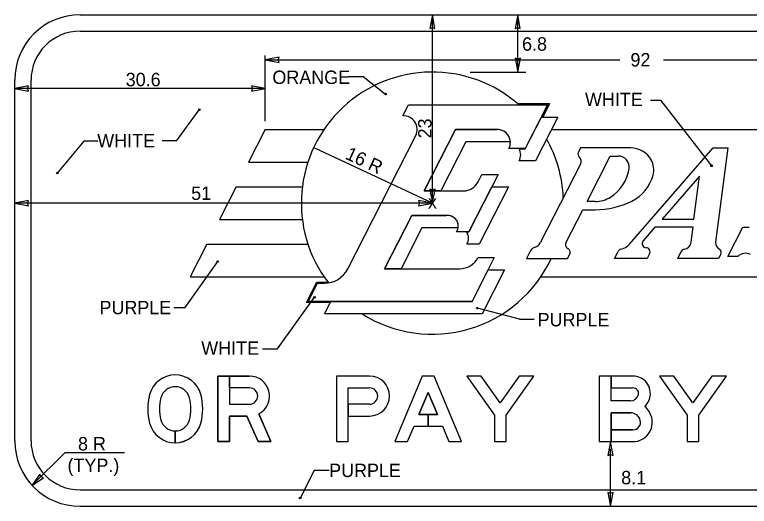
# Model space of a CAD drawing. Extents: x 319706 to 320346, y 1621790 to 1622121.
# Drawn here: x 319726.9 to 319803.6, y 1621939.2 to 1621990.5 of the extents above; entities that cross this region are included whole.
import ezdxf

# ---------------------------------------------------------------- set-up
doc = ezdxf.new("R2010")
doc.units = 0
for name, color, linetype in [('1', 7, 'Continuous'), ('52', 7, 'Continuous'), ('GSBWFill', 7, 'Continuous'), ('GSColorFill', 7, 'Continuous'), ('GSOutline', 7, 'Continuous'), ('SignPanel', 7, 'Continuous')]:
    doc.layers.add(name, color=color, linetype=linetype)

msp = doc.modelspace()

# ---------------------------------------------------------------- linework, layer by layer
at = {"layer": '1'}
for p, q in [((319770.499, 1621970.875), (319770.499, 1621990.54)), ((319779.405, 1621984.554), (319779.405, 1621990.539)), ((319753.057, 1621979.425), (319753.057, 1621986.265)), ((319753.057, 1621985.838), (319790.061, 1621985.838)), ((319794.612, 1621985.838), (319831.717, 1621985.838)), ((319761.71, 1621984.076), (319763.257, 1621984.076)), ((319763.257, 1621984.076), (319765.616, 1621982.255)), ((319774.432, 1621984.554), (319780.26, 1621984.554)), ((319753.057, 1621982.845), (319726.894, 1621982.845)), ((319793.284, 1621981.616), (319794.302, 1621981.616)), ((319794.302, 1621981.616), (319799.636, 1621974.776)), ((319743.826, 1621977.424), (319746.164, 1621980.623)), ((319734.126, 1621977.354), (319731.341, 1621974.017)), ((319735.572, 1621977.354), (319734.126, 1621977.354)), ((319742.279, 1621977.424), (319743.826, 1621977.424)), ((319770.499, 1621970.874), (319758.222, 1621976.599)), ((319755.462, 1621970.875), (319726.894, 1621970.875)), ((319770.499, 1621970.875), (319755.462, 1621970.875)), ((319744.686, 1621959.996), (319748.083, 1621964.786)), ((319754.313, 1621955.659), (319758.192, 1621961.049)), ((319743.5, 1621959.996), (319744.686, 1621959.996)), ((319779.586, 1621958.768), (319775.195, 1621959.917)), ((319779.586, 1621958.768), (319781.134, 1621958.768)), ((319752.765, 1621955.659), (319754.313, 1621955.659)), ((319789.098, 1621939.239), (319789.098, 1621945.224)), ((319728.692, 1621941.392), (319732.154, 1621944.855)), ((319732.154, 1621944.855), (319738.346, 1621944.855)), ((319758.163, 1621942.957), (319756.692, 1621940.103)), ((319759.725, 1621942.957), (319758.163, 1621942.957))]:
    msp.add_line(p, q, dxfattribs=at)
for centre in [(319765.616, 1621982.254), (319746.164, 1621980.621), (319799.635, 1621974.775), (319731.34, 1621974.016), (319748.083, 1621964.784), (319758.192, 1621961.048), (319775.195, 1621959.915), (319775.195, 1621959.915), (319756.692, 1621940.103)]:
    msp.add_circle(centre, 0.0855, dxfattribs=at)
at = {"layer": '52'}
for p, q in [((319770.499, 1621990.54), (319770.219, 1621989.09)), ((319770.769, 1621989.09), (319770.499, 1621990.54)), ((319779.405, 1621990.539), (319779.125, 1621989.089)), ((319779.675, 1621989.089), (319779.405, 1621990.539)), ((319770.219, 1621989.09), (319770.499, 1621989.2)), ((319770.499, 1621989.2), (319770.769, 1621989.09)), ((319779.125, 1621989.089), (319779.405, 1621989.199)), ((319779.405, 1621989.199), (319779.675, 1621989.089)), ((319754.507, 1621986.108), (319753.057, 1621985.838)), ((319753.057, 1621985.838), (319754.507, 1621985.558)), ((319754.397, 1621985.838), (319754.507, 1621986.108)), ((319754.507, 1621985.558), (319754.397, 1621985.838)), ((319779.405, 1621985.894), (319779.135, 1621986.004)), ((319779.135, 1621986.004), (319779.405, 1621984.554)), ((319779.405, 1621984.554), (319779.685, 1621986.004)), ((319779.685, 1621986.004), (319779.405, 1621985.894)), ((319728.344, 1621983.115), (319726.894, 1621982.845)), ((319726.894, 1621982.845), (319728.344, 1621982.565)), ((319728.234, 1621982.845), (319728.344, 1621983.115)), ((319728.344, 1621982.565), (319728.234, 1621982.845)), ((319753.057, 1621982.845), (319751.607, 1621983.125)), ((319751.607, 1621983.125), (319751.717, 1621982.845)), ((319751.717, 1621982.845), (319751.607, 1621982.575)), ((319751.607, 1621982.575), (319753.057, 1621982.845)), ((319770.499, 1621972.215), (319770.229, 1621972.325)), ((319770.229, 1621972.325), (319770.499, 1621970.875)), ((319770.499, 1621970.875), (319770.779, 1621972.325)), ((319770.779, 1621972.325), (319770.499, 1621972.215)), ((319728.344, 1621971.145), (319726.894, 1621970.875)), ((319728.234, 1621970.875), (319728.344, 1621971.145)), ((319770.499, 1621970.875), (319769.049, 1621971.155)), ((319769.049, 1621971.155), (319769.159, 1621970.875)), ((319726.894, 1621970.875), (319728.344, 1621970.595)), ((319728.344, 1621970.595), (319728.234, 1621970.875)), ((319769.159, 1621970.875), (319769.049, 1621970.605)), ((319769.049, 1621970.605), (319770.499, 1621970.875)), ((319789.098, 1621945.988), (319788.818, 1621944.538)), ((319789.368, 1621944.538), (319789.098, 1621945.988)), ((319788.818, 1621944.538), (319789.098, 1621944.648)), ((319789.098, 1621944.648), (319789.368, 1621944.538)), ((319729.526, 1621942.608), (319728.692, 1621941.392)), ((319729.639, 1621942.34), (319729.526, 1621942.608)), ((319728.692, 1621941.392), (319729.915, 1621942.219)), ((319729.915, 1621942.219), (319729.639, 1621942.34)), ((319789.098, 1621940.579), (319788.828, 1621940.689)), ((319788.828, 1621940.689), (319789.098, 1621939.239)), ((319789.098, 1621939.239), (319789.378, 1621940.689)), ((319789.378, 1621940.689), (319789.098, 1621940.579))]:
    msp.add_line(p, q, dxfattribs=at)
at = {"layer": 'GSBWFill'}
for p, q in [((319761.713, 1621951.598), (319763.936, 1621951.598)), ((319743.651, 1621945.868), (319743.651, 1621947.099)), ((319743.651, 1621947.099), (319743.651, 1621945.868))]:
    msp.add_line(p, q, dxfattribs=at)
for points in [[(319752.38, 1621948.897), (319753.64, 1621945.988), (319752.298, 1621945.988), (319751.143, 1621948.656), (319749.33, 1621948.656), (319749.33, 1621945.988), (319748.098, 1621945.988), (319748.098, 1621952.829), (319749.329, 1621952.829), (319749.33, 1621949.887), (319751.406, 1621949.887)], [(319749.33, 1621951.598), (319749.33, 1621952.829), (319751.406, 1621952.829)], [(319763.936, 1621952.829), (319760.481, 1621952.829), (319760.481, 1621945.988), (319761.713, 1621945.988), (319761.713, 1621951.598)], [(319791.174, 1621950.229), (319789.148, 1621950.229), (319789.148, 1621952.829), (319787.916, 1621952.829), (319787.916, 1621945.988), (319789.148, 1621945.988)], [(319791.439, 1621952.829), (319789.148, 1621952.829), (319789.148, 1621951.598), (319791.439, 1621951.598)], [(319751.406, 1621951.598), (319749.33, 1621951.598)], [(319763.936, 1621949.887), (319761.713, 1621949.887), (319761.713, 1621948.656), (319763.936, 1621948.656)], [(319789.148, 1621945.988), (319789.148, 1621948.998), (319791.174, 1621948.998)], [(319791.439, 1621947.219), (319789.148, 1621947.219), (319789.148, 1621945.988), (319791.439, 1621945.988)]]:
    msp.add_lwpolyline(points, dxfattribs=at)
for points in [[(319771.021, 1621948.827), (319770.06, 1621948.827), (319770.06, 1621947.595), (319771.538, 1621947.595), (319772.213, 1621945.988), (319773.549, 1621945.988), (319770.675, 1621952.829), (319769.444, 1621952.829), (319766.57, 1621945.988), (319767.906, 1621945.988), (319768.581, 1621947.595), (319770.06, 1621947.595), (319770.06, 1621948.827), (319769.099, 1621948.827), (319770.06, 1621951.115)], [(319778.201, 1621948.758), (319781.074, 1621952.829), (319779.567, 1621952.829), (319777.585, 1621950.022), (319775.603, 1621952.829), (319774.096, 1621952.829), (319776.97, 1621948.758), (319776.97, 1621945.988), (319778.201, 1621945.988)], [(319798.315, 1621948.758), (319801.189, 1621952.829), (319799.681, 1621952.829), (319797.699, 1621950.022), (319795.718, 1621952.829), (319794.21, 1621952.829), (319797.084, 1621948.758), (319797.084, 1621945.988), (319798.315, 1621945.988)]]:
    msp.add_lwpolyline(points, close=True, dxfattribs=at)
for centre, radius, start, end in [((319743.651, 1621950.176), 2.773, 14.96177, 165.03823), ((319751.406, 1621950.742), 2.087, 297.837, 90), ((319791.439, 1621951.016), 1.813, 345.52249, 90), ((319743.651, 1621950.176), 1.541, 14.96177, 165.03823), ((319751.406, 1621950.742), 0.855, 270, 90), ((319791.439, 1621951.016), 0.582, 345.52249, 90), ((319746.525, 1621949.408), 5.747, 165.03823, 194.96177), ((319746.525, 1621949.408), 4.515, 165.03823, 194.96177), ((319740.778, 1621949.408), 4.515, 345.03823, 14.96177), ((319740.778, 1621949.408), 5.747, 345.03823, 14.96177), ((319791.174, 1621951.084), 0.855, 270, 345.52249), ((319791.174, 1621951.084), 2.087, 316.7114, 345.52249), ((319791.174, 1621947.937), 2.292, 14.47751, 48.4921), ((319791.174, 1621947.937), 1.06, 14.47751, 90), ((319743.651, 1621948.64), 1.541, 194.96177, 270), ((319743.651, 1621948.64), 1.541, 270.01272, 345.03823), ((319791.439, 1621948.006), 2.018, 270, 14.47751), ((319791.439, 1621948.006), 0.787, 270, 14.47751), ((319743.651, 1621948.64), 2.773, 194.96177, 270), ((319743.651, 1621948.64), 2.773, 270.00707, 345.03823)]:
    msp.add_arc(centre, radius, start, end, dxfattribs=at)
for major_axis in [(0, 2.087), (0, 0.855)]:
    msp.add_ellipse((319763.936, 1621950.742), major_axis=major_axis, ratio=0.999994, start_param=3.141593, end_param=6.283185, dxfattribs=at)
at = {"layer": 'GSColorFill'}
for p, q in [((319761.713, 1621951.598), (319763.936, 1621951.598)), ((319743.651, 1621945.868), (319743.651, 1621947.099)), ((319743.651, 1621947.099), (319743.651, 1621945.868))]:
    msp.add_line(p, q, dxfattribs=at)
for points in [[(319752.38, 1621948.897), (319753.64, 1621945.988), (319752.298, 1621945.988), (319751.143, 1621948.656), (319749.33, 1621948.656), (319749.33, 1621945.988), (319748.098, 1621945.988), (319748.098, 1621952.829), (319749.329, 1621952.829), (319749.33, 1621949.887), (319751.406, 1621949.887)], [(319749.33, 1621951.598), (319749.33, 1621952.829), (319751.406, 1621952.829)], [(319763.936, 1621952.829), (319760.481, 1621952.829), (319760.481, 1621945.988), (319761.713, 1621945.988), (319761.713, 1621951.598)], [(319791.174, 1621950.229), (319789.148, 1621950.229), (319789.148, 1621952.829), (319787.916, 1621952.829), (319787.916, 1621945.988), (319789.148, 1621945.988)], [(319791.439, 1621952.829), (319789.148, 1621952.829), (319789.148, 1621951.598), (319791.439, 1621951.598)], [(319751.406, 1621951.598), (319749.33, 1621951.598)], [(319763.936, 1621949.887), (319761.713, 1621949.887), (319761.713, 1621948.656), (319763.936, 1621948.656)], [(319789.148, 1621945.988), (319789.148, 1621948.998), (319791.174, 1621948.998)], [(319791.439, 1621947.219), (319789.148, 1621947.219), (319789.148, 1621945.988), (319791.439, 1621945.988)]]:
    msp.add_lwpolyline(points, dxfattribs=at)
for points in [[(319771.021, 1621948.827), (319770.06, 1621948.827), (319770.06, 1621947.595), (319771.538, 1621947.595), (319772.213, 1621945.988), (319773.549, 1621945.988), (319770.675, 1621952.829), (319769.444, 1621952.829), (319766.57, 1621945.988), (319767.906, 1621945.988), (319768.581, 1621947.595), (319770.06, 1621947.595), (319770.06, 1621948.827), (319769.099, 1621948.827), (319770.06, 1621951.115)], [(319778.201, 1621948.758), (319781.074, 1621952.829), (319779.567, 1621952.829), (319777.585, 1621950.022), (319775.603, 1621952.829), (319774.096, 1621952.829), (319776.97, 1621948.758), (319776.97, 1621945.988), (319778.201, 1621945.988)], [(319798.315, 1621948.758), (319801.189, 1621952.829), (319799.681, 1621952.829), (319797.699, 1621950.022), (319795.718, 1621952.829), (319794.21, 1621952.829), (319797.084, 1621948.758), (319797.084, 1621945.988), (319798.315, 1621945.988)]]:
    msp.add_lwpolyline(points, close=True, dxfattribs=at)
for centre, radius, start, end in [((319743.651, 1621950.176), 2.773, 14.96177, 165.03823), ((319751.406, 1621950.742), 2.087, 297.837, 90), ((319791.439, 1621951.016), 1.813, 345.52249, 90), ((319743.651, 1621950.176), 1.541, 14.96177, 165.03823), ((319751.406, 1621950.742), 0.855, 270, 90), ((319791.439, 1621951.016), 0.582, 345.52249, 90), ((319746.525, 1621949.408), 5.747, 165.03823, 194.96177), ((319746.525, 1621949.408), 4.515, 165.03823, 194.96177), ((319740.778, 1621949.408), 4.515, 345.03823, 14.96177), ((319740.778, 1621949.408), 5.747, 345.03823, 14.96177), ((319791.174, 1621951.084), 0.855, 270, 345.52249), ((319791.174, 1621951.084), 2.087, 316.7114, 345.52249), ((319791.174, 1621947.937), 2.292, 14.47751, 48.4921), ((319791.174, 1621947.937), 1.06, 14.47751, 90), ((319743.651, 1621948.64), 1.541, 194.96177, 270), ((319743.651, 1621948.64), 1.541, 270.01272, 345.03823), ((319791.439, 1621948.006), 2.018, 270, 14.47751), ((319791.439, 1621948.006), 0.787, 270, 14.47751), ((319743.651, 1621948.64), 2.773, 194.96177, 270), ((319743.651, 1621948.64), 2.773, 270.00707, 345.03823)]:
    msp.add_arc(centre, radius, start, end, dxfattribs=at)
for major_axis in [(0, 2.087), (0, 0.855)]:
    msp.add_ellipse((319763.936, 1621950.742), major_axis=major_axis, ratio=0.999994, start_param=3.141593, end_param=6.283185, dxfattribs=at)
at = {"layer": 'GSOutline'}
for p, q in [((319761.713, 1621951.598), (319763.936, 1621951.598)), ((319761.713, 1621948.656), (319763.936, 1621948.656)), ((319787.916, 1621945.988), (319791.439, 1621945.988))]:
    msp.add_line(p, q, dxfattribs=at)
for points in [[(319751.406, 1621952.829), (319748.098, 1621952.829), (319748.098, 1621945.988), (319749.33, 1621945.988), (319749.33, 1621948.656), (319751.143, 1621948.656), (319752.298, 1621945.988), (319753.64, 1621945.988), (319752.38, 1621948.897)], [(319763.936, 1621952.829), (319760.481, 1621952.829), (319760.481, 1621945.988), (319761.713, 1621945.988), (319761.713, 1621948.656)], [(319791.439, 1621952.829), (319787.916, 1621952.829), (319787.916, 1621945.988)], [(319751.406, 1621951.598), (319749.33, 1621951.598), (319749.33, 1621949.887), (319751.406, 1621949.887)], [(319763.936, 1621949.887), (319761.713, 1621949.887), (319761.713, 1621951.598)], [(319791.174, 1621950.229), (319789.148, 1621950.229), (319789.148, 1621951.598), (319791.439, 1621951.598)], [(319791.174, 1621948.998), (319789.148, 1621948.998), (319789.148, 1621947.219), (319791.439, 1621947.219)]]:
    msp.add_lwpolyline(points, dxfattribs=at)
for points in [[(319768.581, 1621947.595), (319771.538, 1621947.595), (319772.213, 1621945.988), (319773.549, 1621945.988), (319770.675, 1621952.829), (319769.444, 1621952.829), (319766.57, 1621945.988), (319767.906, 1621945.988)], [(319778.201, 1621948.758), (319781.074, 1621952.829), (319779.567, 1621952.829), (319777.585, 1621950.022), (319775.603, 1621952.829), (319774.096, 1621952.829), (319776.97, 1621948.758), (319776.97, 1621945.988), (319778.201, 1621945.988)], [(319798.315, 1621948.758), (319801.189, 1621952.829), (319799.681, 1621952.829), (319797.699, 1621950.022), (319795.718, 1621952.829), (319794.21, 1621952.829), (319797.084, 1621948.758), (319797.084, 1621945.988), (319798.315, 1621945.988)], [(319771.021, 1621948.827), (319770.06, 1621951.115), (319769.099, 1621948.827)]]:
    msp.add_lwpolyline(points, close=True, dxfattribs=at)
for centre, radius, start, end in [((319743.651, 1621950.176), 2.773, 14.96177, 165.03823), ((319751.406, 1621950.742), 2.087, 297.837, 90), ((319791.439, 1621951.016), 1.813, 345.52249, 90), ((319743.651, 1621950.176), 1.541, 14.96177, 165.03823), ((319751.406, 1621950.742), 0.855, 270, 90), ((319791.439, 1621951.016), 0.582, 345.52249, 90), ((319746.525, 1621949.408), 5.747, 165.03823, 194.96177), ((319746.525, 1621949.408), 4.515, 165.03823, 194.96177), ((319740.778, 1621949.408), 4.515, 345.03823, 14.96177), ((319740.778, 1621949.408), 5.747, 345.03823, 14.96177), ((319791.174, 1621951.084), 0.855, 270, 345.52249), ((319791.174, 1621951.084), 2.087, 316.7114, 345.52249), ((319791.174, 1621947.937), 2.292, 14.47751, 48.4921), ((319791.174, 1621947.937), 1.06, 14.47751, 90), ((319743.651, 1621948.64), 1.541, 194.96177, 345.03823), ((319791.439, 1621948.006), 2.018, 270, 14.47751), ((319791.439, 1621948.006), 0.787, 270, 14.47751), ((319743.651, 1621948.64), 2.773, 194.96177, 345.03823)]:
    msp.add_arc(centre, radius, start, end, dxfattribs=at)
for major_axis in [(0, 2.087), (0, 0.855)]:
    msp.add_ellipse((319763.936, 1621950.742), major_axis=major_axis, ratio=0.999994, start_param=3.141593, end_param=6.283185, dxfattribs=at)
at = {"layer": 'SignPanel'}
for p, q in [((319733.734, 1621990.539), (319843.174, 1621990.539)), ((319733.734, 1621988.829), (319843.174, 1621988.829)), ((319726.894, 1621946.079), (319726.894, 1621983.699)), ((319728.604, 1621946.079), (319728.604, 1621983.699)), ((319767.405, 1621979.987), (319767.988, 1621981.134)), ((319767.988, 1621981.134), (319782.523, 1621981.134)), ((319779.399, 1621981.262), (319782.732, 1621981.262)), ((319782.523, 1621981.134), (319780.195, 1621976.563)), ((319782.732, 1621981.262), (319782.013, 1621979.852)), ((319780.192, 1621976.558), (319781.871, 1621979.852)), ((319780.192, 1621976.558), (319781.871, 1621979.852)), ((319783.598, 1621979.852), (319781.268, 1621975.28)), ((319783.598, 1621979.852), (319781.268, 1621975.28)), ((319781.871, 1621979.852), (319783.598, 1621979.852)), ((319781.871, 1621979.852), (319783.598, 1621979.852)), ((319753.057, 1621978.569), (319751.316, 1621975.149)), ((319753.057, 1621978.569), (319759.188, 1621978.569)), ((319761.66, 1621964.012), (319768.756, 1621977.94)), ((319772.914, 1621978.569), (319769.647, 1621972.157)), ((319769.647, 1621972.157), (319772.914, 1621978.569)), ((319769.647, 1621972.157), (319772.914, 1621978.569)), ((319777.272, 1621978.569), (319772.914, 1621978.569)), ((319772.914, 1621978.569), (319777.272, 1621978.569)), ((319772.914, 1621978.569), (319777.272, 1621978.569)), ((319782.943, 1621978.569), (319831.717, 1621978.569)), ((319773.988, 1621977.287), (319771.374, 1621972.157)), ((319773.988, 1621977.287), (319771.374, 1621972.157)), ((319778.639, 1621977.287), (319773.988, 1621977.287)), ((319778.639, 1621977.287), (319773.988, 1621977.287)), ((319780.195, 1621976.563), (319778.484, 1621976.563)), ((319779.556, 1621976.558), (319780.192, 1621976.558)), ((319779.556, 1621976.558), (319780.192, 1621976.558)), ((319785.974, 1621976.645), (319785.741, 1621976.189)), ((319791.21, 1621976.645), (319785.974, 1621976.645)), ((319791.079, 1621966.604), (319799.81, 1621976.645)), ((319799.81, 1621976.645), (319801.349, 1621976.645)), ((319801.349, 1621976.645), (319800.069, 1621966.806)), ((319786.645, 1621971.045), (319789.064, 1621975.79)), ((319789.064, 1621975.79), (319789.888, 1621975.79)), ((319751.316, 1621975.149), (319757.504, 1621975.149)), ((319781.268, 1621975.28), (319779.558, 1621975.28)), ((319781.268, 1621975.28), (319779.558, 1621975.28)), ((319785.989, 1621975.029), (319781.755, 1621966.721)), ((319777.367, 1621973.867), (319774.318, 1621967.882)), ((319775.261, 1621973.09), (319775.657, 1621973.867)), ((319775.657, 1621973.867), (319777.367, 1621973.867)), ((319798.378, 1621973.696), (319794.475, 1621969.206)), ((319797.794, 1621969.206), (319798.378, 1621973.696)), ((319750.011, 1621972.584), (319748.27, 1621969.164)), ((319750.011, 1621972.584), (319756.925, 1621972.584)), ((319774.318, 1621967.882), (319776.714, 1621972.584)), ((319774.318, 1621967.882), (319776.714, 1621972.584)), ((319778.441, 1621972.584), (319775.391, 1621966.599)), ((319778.441, 1621972.584), (319775.391, 1621966.599)), ((319776.714, 1621972.584), (319778.441, 1621972.584)), ((319776.714, 1621972.584), (319778.441, 1621972.584)), ((319769.647, 1621972.157), (319773.738, 1621972.157)), ((319771.374, 1621972.157), (319769.647, 1621972.157)), ((319771.374, 1621972.157), (319769.647, 1621972.157)), ((319787.492, 1621971.045), (319786.645, 1621971.045)), ((319784.441, 1621966.721), (319786.209, 1621970.19)), ((319786.209, 1621970.19), (319787.492, 1621970.19)), ((319768.341, 1621969.592), (319765.509, 1621964.034)), ((319765.509, 1621964.034), (319768.341, 1621969.592)), ((319765.509, 1621964.034), (319768.341, 1621969.592)), ((319772.093, 1621969.592), (319768.341, 1621969.592)), ((319768.341, 1621969.592), (319771.932, 1621969.58)), ((319768.341, 1621969.592), (319771.932, 1621969.58)), ((319748.27, 1621969.164), (319756.925, 1621969.164)), ((319794.475, 1621969.206), (319797.794, 1621969.206)), ((319769.413, 1621968.306), (319767.236, 1621964.034)), ((319769.413, 1621968.306), (319767.236, 1621964.034)), ((319773.188, 1621968.294), (319769.413, 1621968.306)), ((319773.188, 1621968.294), (319769.413, 1621968.306)), ((319774.318, 1621967.882), (319773.03, 1621967.882)), ((319774.049, 1621967.882), (319774.318, 1621967.882)), ((319774.049, 1621967.882), (319774.318, 1621967.882)), ((319793.734, 1621968.351), (319792.494, 1621966.927)), ((319797.707, 1621968.351), (319793.734, 1621968.351)), ((319797.504, 1621966.806), (319797.707, 1621968.351)), ((319801.343, 1621965.317), (319802.895, 1621968.364)), ((319802.895, 1621968.364), (319803.582, 1621968.364)), ((319746.964, 1621966.599), (319745.223, 1621963.179)), ((319746.964, 1621966.599), (319757.504, 1621966.599)), ((319775.391, 1621966.599), (319774.109, 1621966.599)), ((319775.391, 1621966.599), (319774.109, 1621966.599)), ((319780.716, 1621965.857), (319780.332, 1621965.102)), ((319789.506, 1621965.102), (319789.878, 1621965.834)), ((319793.178, 1621965.596), (319792.926, 1621965.102)), ((319796.104, 1621965.102), (319796.482, 1621965.845)), ((319776.963, 1621965.185), (319774.634, 1621960.614)), ((319775.252, 1621965.185), (319776.963, 1621965.185)), ((319780.332, 1621965.102), (319784.607, 1621965.102)), ((319784.607, 1621965.102), (319784.839, 1621965.56)), ((319792.926, 1621965.102), (319789.506, 1621965.102)), ((319800.379, 1621965.102), (319796.104, 1621965.102)), ((319800.604, 1621965.543), (319800.379, 1621965.102)), ((319802.382, 1621965.317), (319801.343, 1621965.317)), ((319765.509, 1621964.034), (319773.356, 1621964.034)), ((319767.236, 1621964.034), (319765.509, 1621964.034)), ((319767.236, 1621964.034), (319765.509, 1621964.034)), ((319774.634, 1621960.614), (319776.309, 1621963.903)), ((319774.634, 1621960.614), (319776.309, 1621963.903)), ((319778.037, 1621963.903), (319775.707, 1621959.332)), ((319778.037, 1621963.903), (319775.707, 1621959.332)), ((319776.309, 1621963.903), (319778.037, 1621963.903)), ((319776.309, 1621963.903), (319778.037, 1621963.903)), ((319745.223, 1621963.179), (319759.188, 1621963.179)), ((319757.351, 1621960.502), (319758.435, 1621962.63)), ((319757.534, 1621960.614), (319758.504, 1621962.518)), ((319758.435, 1621962.63), (319759.222, 1621962.63)), ((319758.504, 1621962.518), (319759.222, 1621962.518)), ((319781.809, 1621963.179), (319823.875, 1621963.179)), ((319759.84, 1621960.502), (319757.351, 1621960.502)), ((319774.634, 1621960.614), (319757.534, 1621960.614)), ((319759.244, 1621959.332), (319759.897, 1621960.614)), ((319759.244, 1621959.332), (319759.897, 1621960.614)), ((319759.897, 1621960.614), (319774.634, 1621960.614)), ((319759.897, 1621960.614), (319774.634, 1621960.614)), ((319775.707, 1621959.332), (319759.244, 1621959.332)), ((319775.707, 1621959.332), (319759.244, 1621959.332)), ((319733.734, 1621940.949), (319843.174, 1621940.949)), ((319733.734, 1621939.239), (319843.174, 1621939.239))]:
    msp.add_line(p, q, dxfattribs=at)
for centre, radius, start, end in [((319733.733, 1621983.698), 6.84, 90, 180), ((319733.733, 1621983.698), 5.13, 90, 180), ((319770.498, 1621970.873), 13.68, 48.59038, 217.4727), ((319767.498, 1621978.579), 1.411, 332.99985, 93.80449), ((319777.273, 1621977.2), 1.368, 332.20885, 90), ((319777.273, 1621977.2), 1.368, 3.58332, 90), ((319777.273, 1621977.2), 1.368, 3.58332, 90), ((319770.498, 1621970.873), 13.68, 2.42356, 29.27706), ((319778.347, 1621975.917), 1.368, 332.20885, 27.91266), ((319778.347, 1621975.917), 1.368, 332.20885, 27.91266), ((319791.21, 1621974.207), 2.437, 29.43149, 90), ((319786.121, 1621975.994), 0.428, 152.97842, 231.16017), ((319785.531, 1621975.261), 0.513, 333.00266, 51.16017), ((319789.887, 1621974.635), 1.154, 351.07601, 90), ((319791.47, 1621974.354), 2.138, 344.70738, 29.43149), ((319786.804, 1621975.119), 4.275, 302.42062, 351.07601), ((319789.409, 1621974.918), 4.275, 296.64315, 344.70738), ((319773.738, 1621973.865), 1.71, 270, 332.98829), ((319787.492, 1621974.036), 2.993, 270, 302.42062), ((319787.492, 1621978.739), 8.55, 270, 296.64315), ((319772.093, 1621968.479), 1.111, 350.35016, 98.33436), ((319772.093, 1621968.479), 1.111, 350.35016, 98.33436), ((319772.093, 1621968.479), 1.111, 327.42103, 90), ((319773.173, 1621967.196), 1.111, 327.42103, 37.97987), ((319773.173, 1621967.196), 1.111, 327.42103, 37.97987), ((319780.994, 1621967.107), 0.855, 286.43167, 332.99588), ((319784.822, 1621966.526), 0.427, 152.98839, 244.78323), ((319789.789, 1621967.724), 1.71, 282.71621, 318.99659), ((319792.817, 1621966.645), 0.427, 138.98241, 268.68694), ((319796.657, 1621966.915), 0.855, 279.2397, 352.56317), ((319800.747, 1621966.717), 0.684, 172.58839, 241.86732), ((319781.477, 1621965.467), 0.855, 106.43168, 152.97425), ((319784.458, 1621965.752), 0.427, 333.02391, 64.78322), ((319790.259, 1621965.639), 0.427, 102.71621, 153.02391), ((319792.797, 1621965.79), 0.427, 332.97842, 88.68694), ((319796.863, 1621965.65), 0.428, 99.2397, 153.02391), ((319800.223, 1621965.736), 0.427, 332.97842, 61.86732), ((319803.201, 1621964.443), 1.197, 64.37946, 133.18921), ((319770.498, 1621970.873), 13.68, 237.53826, 335.04698), ((319773.355, 1621966.17), 2.138, 270, 332.5096), ((319759.222, 1621965.254), 2.736, 270, 332.99913), ((319759.222, 1621965.254), 2.625, 270, 277.50379), ((319733.733, 1621946.078), 6.84, 180, 270), ((319733.733, 1621946.078), 5.13, 180, 270)]:
    msp.add_arc(centre, radius, start, end, dxfattribs=at)

# ---------------------------------------------------------------- texts
at = {"layer": '1'}
for s, p in [('6.8', (319779.859, 1621986.784)), ('92', (319791.173, 1621985.137)), ('30.6', (319738.486, 1621983.075)), ('ORANGE', (319753.795, 1621983.31)), ('WHITE', (319786.428, 1621980.998)), ('WHITE', (319735.514, 1621976.695)), ('51', (319745.319, 1621971.211)), ('x', (319770.038, 1621970.302)), ('PURPLE', (319735.746, 1621959.279)), ('PURPLE', (319781.484, 1621958.015)), ('WHITE', (319746.367, 1621955.047)), ('8 R', (319733.503, 1621945.069)), ('(TYP.)', (319732.407, 1621942.814)), ('PURPLE', (319759.722, 1621942.285)), ('8.1', (319790.21, 1621941.532))]:
    msp.add_text(s, height=1.4, dxfattribs=at).set_placement(p)
for s, rotation, p in [('23', 90, (319770.402, 1621977.633)), ('16 R', 334.99906, (319761.305, 1621975.545))]:
    msp.add_text(s, height=1.4, rotation=rotation, dxfattribs=at).set_placement(p)

doc.saveas('drawing.dxf')
